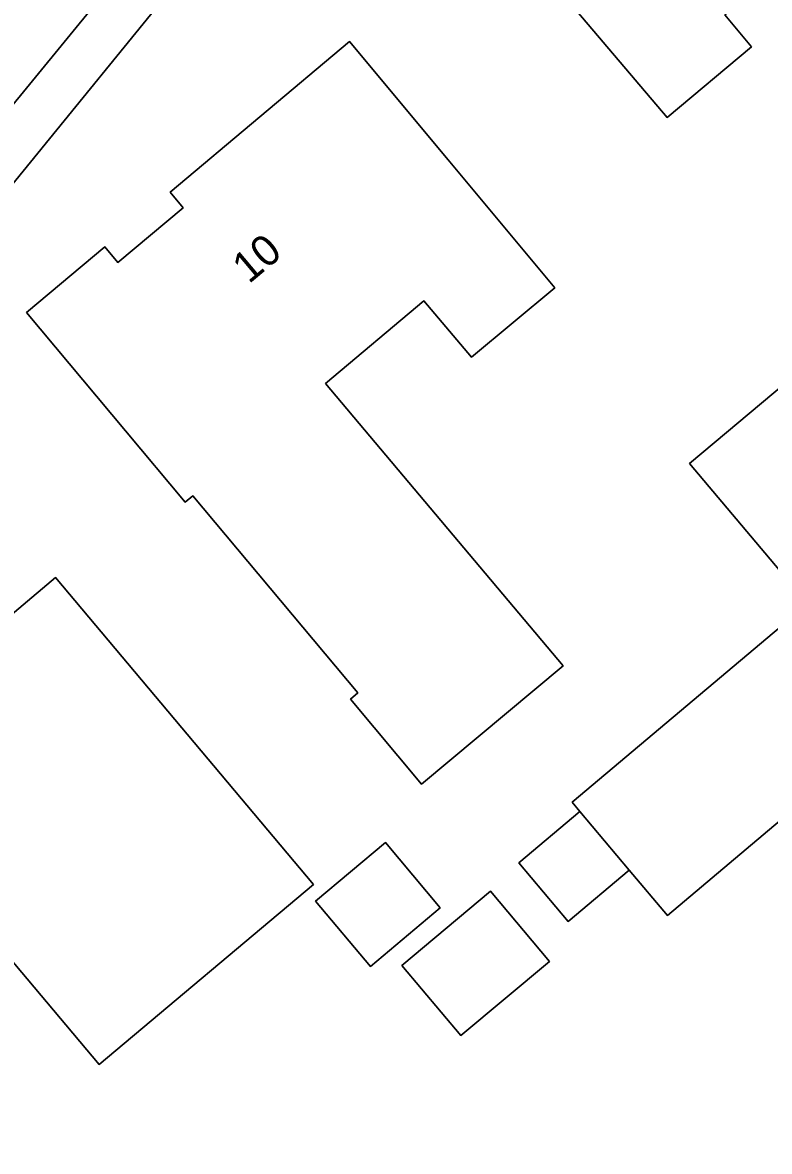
# Model space of a CAD drawing. Extents: x 157320 to 158835, y 386650 to 388491.
# Drawn here: x 157848.54 to 157872.77, y 387256.81 to 387293.47 of the extents above; entities that cross this region are included whole.
import ezdxf

# ---------------------------------------------------------------- set-up
doc = ezdxf.new("R2010")
doc.units = 0
for name, color, linetype in [('IMGEO_Erf', 7, 'Continuous'), ('IMGEO_Groenvoorziening', 7, 'Continuous'), ('IMGEO_Pand', 7, 'Continuous'), ('IMGEO_Pand_nummerreeks', 7, 'Continuous'), ('IMGEO_Rijbaan_lokaal_gesloten', 7, 'Continuous')]:
    doc.layers.add(name, color=color, linetype=linetype)

msp = doc.modelspace()

# ---------------------------------------------------------------- linework, layer by layer
at = {"layer": 'IMGEO_Erf'}
msp.add_lwpolyline([(157877.463, 387323.953), (157870.232, 387315.116), (157867.191, 387311.426), (157860.133, 387302.866), (157857.9, 387300.028), (157855.249, 387296.878), (157844.036, 387283.095), (157841.434, 387279.859), (157832.697, 387269.133), (157832.809, 387268.088), (157837.144, 387262.839), (157837.774, 387262.109), (157847.884, 387250), (157860.639, 387234.724), (157864.481, 387234.155), (157870.893, 387238.359), (157872.559, 387239.456), (157873.603, 387240.168)], dxfattribs=at)
for points in [[(157878.314, 387292.263), (157874.702, 387296.559), (157871.324, 387293.719), (157872.194, 387292.685), (157869.452, 387290.38), (157866.346, 387294.059), (157866.957, 387294.575), (157863.664, 387298.476), (157869.733, 387303.58), (157870.376, 387302.817), (157873.673, 387305.596), (157874.366, 387304.764), (157877.135, 387307.071), (157880.362, 387303.252), (157884.939, 387297.833)], [(157858.366, 387281.748), (157866.078, 387272.58), (157861.484, 387268.735), (157859.175, 387271.494), (157859.42, 387271.699), (157854.062, 387278.103), (157853.816, 387277.898), (157851.878, 387280.213), (157848.669, 387284.048), (157851.21, 387286.183), (157851.634, 387285.678), (157853.747, 387287.453), (157853.323, 387287.958), (157859.149, 387292.854), (157862.349, 387289.012), (157865.812, 387284.853), (157863.107, 387282.601), (157861.563, 387284.436)], [(157877.121, 387270.935), (157869.462, 387264.475), (157868.223, 387265.946), (157866.245, 387264.281), (157864.648, 387266.178), (157866.626, 387267.843), (157866.37, 387268.147), (157874.02, 387274.587), (157870.177, 387279.152), (157873.314, 387281.776), (157877.134, 387277.208), (157874.054, 387274.547)], [(157857.979, 387265.482), (157851.022, 387259.637), (157847.422, 387263.906), (157844.963, 387266.822), (157844.635, 387266.545), (157842.436, 387266.745), (157842.173, 387267.062), (157839.382, 387264.742), (157836.113, 387268.651), (157840.414, 387272.266), (157843.233, 387274.635), (157842.583, 387275.408), (157844.173, 387276.756), (157847.08, 387273.312), (157849.608, 387275.446)], [(157862.094, 387264.72), (157859.825, 387262.814), (157858.045, 387264.933), (157860.314, 387266.839)], [(157865.633, 387262.982), (157862.761, 387260.57), (157860.847, 387262.849), (157863.719, 387265.261)]]:
    msp.add_lwpolyline(points, close=True, dxfattribs=at)
at = {"layer": 'IMGEO_Groenvoorziening'}
msp.add_lwpolyline([(157844.036, 387283.095), (157855.249, 387296.878), (157854.003, 387297.87), (157842.777, 387284.159)], close=True, dxfattribs=at)
at = {"layer": 'IMGEO_Pand'}
for points in [[(157880.362, 387303.252), (157877.135, 387307.071), (157874.366, 387304.764), (157873.673, 387305.596), (157870.376, 387302.817), (157869.733, 387303.58), (157863.664, 387298.476), (157866.957, 387294.575), (157866.346, 387294.059), (157869.452, 387290.38), (157872.194, 387292.685), (157871.324, 387293.719), (157874.702, 387296.559), (157878.314, 387292.263), (157884.939, 387297.833)], [(157862.349, 387289.012), (157859.149, 387292.854), (157853.323, 387287.958), (157853.747, 387287.453), (157851.634, 387285.678), (157851.21, 387286.183), (157848.669, 387284.048), (157851.878, 387280.213), (157853.816, 387277.898), (157854.062, 387278.103), (157859.42, 387271.699), (157859.175, 387271.494), (157861.484, 387268.735), (157866.078, 387272.58), (157858.366, 387281.748), (157861.563, 387284.436), (157863.107, 387282.601), (157865.812, 387284.853)], [(157873.314, 387281.776), (157870.177, 387279.152), (157874.02, 387274.587), (157874.054, 387274.547), (157877.134, 387277.208)], [(157842.583, 387275.408), (157843.233, 387274.635), (157840.414, 387272.266), (157836.113, 387268.651), (157839.382, 387264.742), (157842.173, 387267.062), (157842.436, 387266.745), (157844.635, 387266.545), (157844.963, 387266.822), (157847.422, 387263.906), (157851.022, 387259.637), (157857.979, 387265.482), (157849.608, 387275.446), (157847.08, 387273.312), (157844.173, 387276.756)], [(157877.121, 387270.935), (157874.054, 387274.547), (157874.02, 387274.587), (157866.37, 387268.147), (157866.626, 387267.843), (157868.223, 387265.946), (157869.462, 387264.475)], [(157866.626, 387267.843), (157864.648, 387266.178), (157866.245, 387264.281), (157868.223, 387265.946)], [(157858.045, 387264.933), (157859.825, 387262.814), (157862.094, 387264.72), (157860.314, 387266.839)], [(157862.761, 387260.57), (157865.633, 387262.982), (157863.719, 387265.261), (157860.847, 387262.849)]]:
    msp.add_lwpolyline(points, close=True, dxfattribs=at)
at = {"layer": 'IMGEO_Rijbaan_lokaal_gesloten'}
msp.add_lwpolyline([(157873.714, 387330.931), (157872.34, 387329.219), (157863.99, 387318.983), (157861.845, 387316.353), (157859.299, 387313.249), (157849.004, 387300.628), (157846.428, 387297.465), (157840.61, 387290.35), (157839.998, 387289.588), (157836.403, 387285.21), (157833.104, 387281.193), (157837.45, 387277.644), (157840.17, 387280.975), (157842.777, 387284.159), (157854.003, 387297.87), (157856.608, 387301.082), (157858.899, 387303.881), (157865.924, 387312.463), (157868.951, 387316.187), (157875.893, 387324.643)], dxfattribs=at)

# ---------------------------------------------------------------- texts
at = {"layer": 'IMGEO_Pand_nummerreeks'}
msp.add_text('10', height=1, rotation=40.0326, dxfattribs=at).set_placement((157855.881, 387284.962))

doc.saveas('drawing.dxf')
